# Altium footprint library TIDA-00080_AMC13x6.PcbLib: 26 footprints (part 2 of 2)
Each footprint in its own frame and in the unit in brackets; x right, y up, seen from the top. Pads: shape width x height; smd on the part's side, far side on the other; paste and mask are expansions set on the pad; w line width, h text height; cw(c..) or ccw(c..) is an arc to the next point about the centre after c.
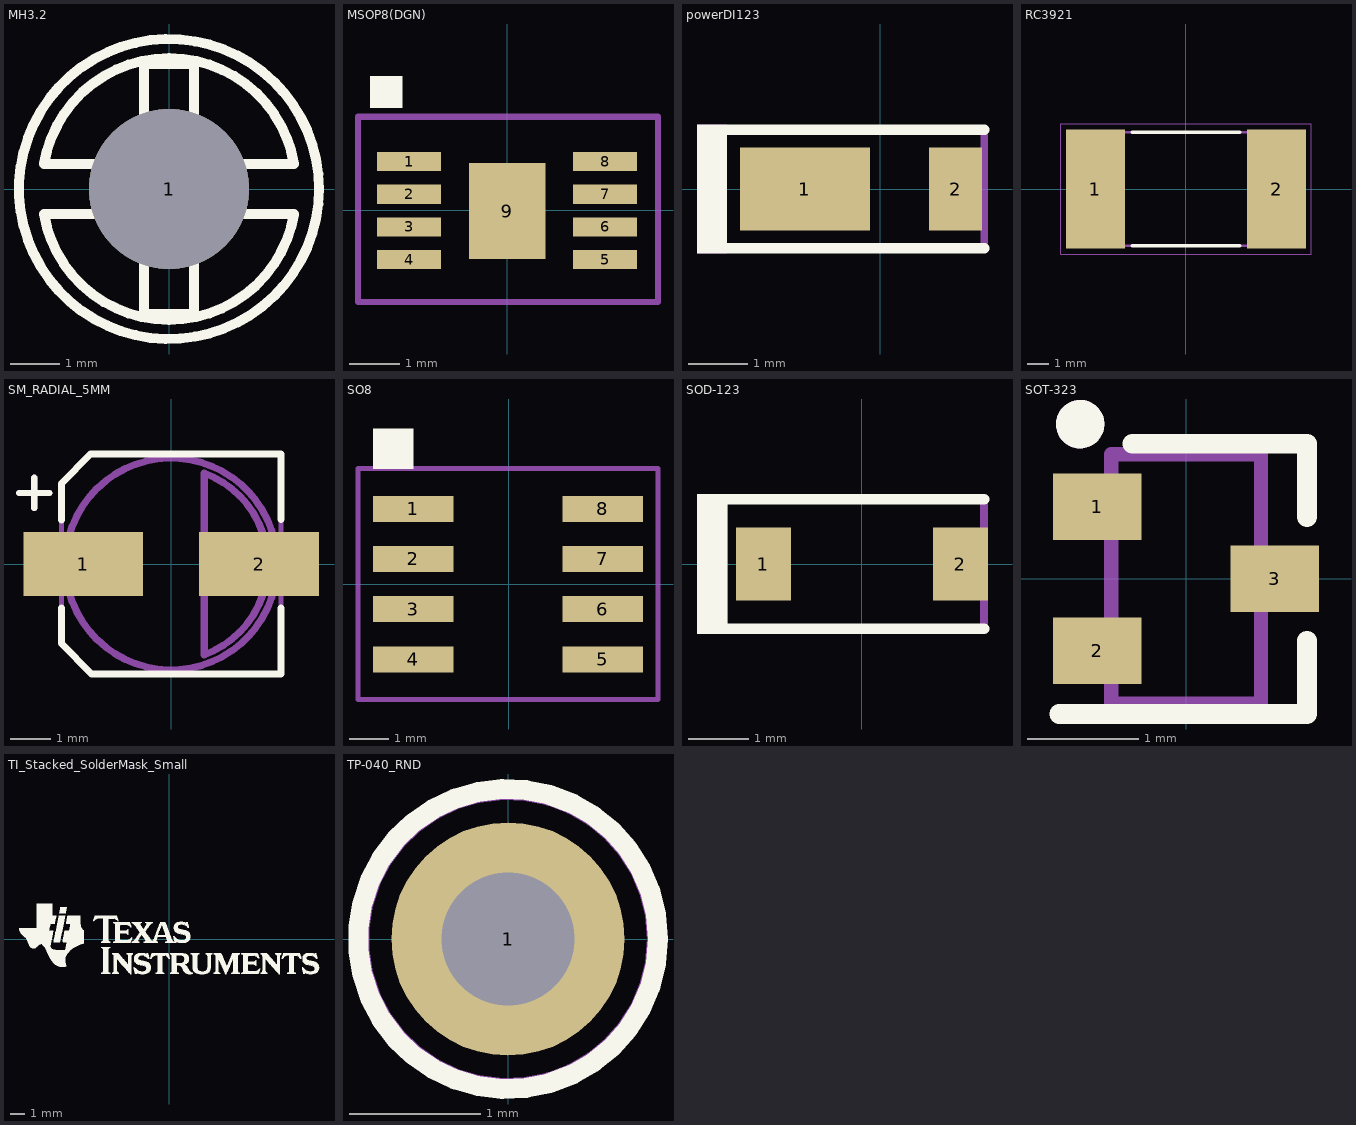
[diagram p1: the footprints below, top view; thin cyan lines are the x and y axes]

## MH3.2 [mil]
height 80
pads (1):
  round 128 / inner round 142 / far side round 128 hole 128 unplated mask+10: 1(0,0)
Top Overlay:
  circle w8: c0,0 r120
  lines w8: -100,-20 -20,-20 -20,-100 20,-100 20,-20 100,-20 ; -100.02,-19.91 ccw(c0,-3.35) 99.99,-20.08 ; -100,20 -20,20 -20,100 20,100 20,20 100,20 ; -99.99,20.09 cw(c0,3.36) 100.02,19.92

## MSOP8(DGN) [mil]
pads (9):
  rect 50x15 smd mask+3: 1(-77,38) 2(-77,12.4) 3(-77,-13.2) 4(-77,-38.8) 5(76.6,-38.8) 6(76.6,-13.2) 7(76.6,12.4) 8(76.6,38)
  rect 60x75 smd: 9(0,-0.8)
Top Overlay:
  region: -107.5,105 -82.5,105 -82.5,80 -107.5,80
Mechanical 5:
  lines w5: -117,-72 -117,73 118,73 118,-72 -117,-72
  text ".Designator" at 15,-20 h25
  text "*" at -105,30 h25

## powerDI123 [mm] "Diodes Inc recommended land pattern, document number DS30628 Rev. 6-2"
height 1
pads (2):
  rect 2.2x1.4 smd: 1(-1.275,0)
  rect 0.9x1.4 smd: 2(1.275,0)
Top Overlay:
  rectangle: -3.099,-1.092 -2.591,1.092
  lines w0.178: -2.946,-1.003 1.759,-1.003 ; -2.946,1.003 1.759,1.003
Mechanical 5:
  rectangle: -3.099,-1.092 -2.591,1.092
  lines w0.127: -2.946,-1.003 1.759,-1.003 1.759,1.003 -2.946,1.003
  text ".Designator" at -0.968,-0.366 h0.64
3D body "PowerDI123.stp": height 1, standoff 0, extent -2.375,-0.965 1.525,0.965

## RC3921 [mm] "RESISTOR, SMD, 3921"
height 0.93
pads (2):
  rect 2.7x5.45 smd mask+0.102: 1(-4.15,0) 2(4.15,0)
Top Overlay:
  lines w0.178: -2.45,-2.6 2.45,-2.6 ; -2.45,2.6 2.45,2.6
Mechanical 5:
  lines w0.127: -5,-2.6 -5,2.6 5,2.6 5,-2.6 -5,-2.6
  text ".Designator" at -0.66,-0.381 h0.64
Mechanical 15:
  lines w0.05: -5.75,-3 5.75,-3 5.75,3 -5.75,3 -5.75,-3
3D body: height 0.93, standoff 0, extent -5,-2.6 5,2.6

## SM_RADIAL_5MM [mm] "Nichicon 5x5.8"
height 6.1
pads (2):
  rect 3x1.6 smd: 1(-2.2,0) 2(2.2,0)
Top Overlay:
  lines w0.152: -3.81,1.778 -3.048,1.778 ; -3.429,1.397 -3.429,2.159
  lines w0.178: -2.75,-1.108 -2.75,-1.992 -1.992,-2.75 2.75,-2.75 2.75,-1.108 ; -2.75,1.108 -2.75,2.019 -2.019,2.75 2.75,2.75 2.75,1.118
Mechanical 5:
  lines w0.127: -2.75,-1.992 -2.75,2.019 -2.019,2.75 2.75,2.75 2.75,-2.75 -1.992,-2.75 -2.75,-1.992
  lines w0.152: -3.81,1.778 -3.048,1.778 ; -3.429,1.397 -3.429,2.159
  text ".Designator" at -0.372,1.111 h0.64
Mechanical 13:
  circle w0.178: c0,0 r2.65
  lines w0.178: 0.827,-2.273 ccw(c0,0) 0.827,2.273 0.827,-2.273
3D body: height 1, standoff 0, extent -2.751,-2.751 2.751,2.751
3D body: height 6.1, standoff 1, extent -2.649,-2.649 2.649,2.649
3D body: height 6.1, standoff 6, extent 0.827,-2.274 2.42,2.274

## SO8 [mil]
pads (8):
  rect 80x26 smd: 1(-95,75) 2(-95,25) 3(-95,-25) 4(-95,-75) 5(94,-75) 6(94,-25) 7(94,25) 8(94,75)
Top Overlay:
  region: -95,115 -95,155 -135,155 -135,115
Mechanical 5:
  lines w5: -150,-115 -150,115 149,115 149,-115 -150,-115
  text "*" at -55.9,51.4 h25
  text ".Designator" at -28.61,-6.81 h25

## SOD-123 [mm] "On Semi recommended land pattern"
height 1.35
pads (2):
  rect 0.915x1.22 smd: 1(-1.637,0) 2(1.637,0)
Top Overlay:
  rectangle: -2.743,-1.168 -2.235,1.168
  lines w0.178: -2.413,-1.079 2.032,-1.079 ; -2.413,1.079 2.032,1.079
Mechanical 5:
  rectangle: -2.743,-1.168 -2.235,1.168
  lines w0.127: -2.413,-1.079 2.032,-1.079 2.032,1.079 -2.413,1.079
  text ".Designator" at 0.762,0.381 h0.64
3D body "SOD-123.stp": height 1.35, standoff 0, extent -1.932,-0.9 1.932,0.9

## SOT-323 [mm] "Zetex recommended land pattern.  March 2007"
height 1.1
pads (3):
  rect 0.8x0.6 smd: 1(-0.8,0.65) 2(-0.8,-0.65) 3(0.8,0)
Top Overlay:
  circle w0.254: c-0.955,1.397 r0.092
  lines w0.178: -1.143,-1.219 1.092,-1.219 1.092,-0.559 ; -0.483,1.219 1.092,1.219 1.092,0.559
Mechanical 5:
  circle w0.254: c-0.955,1.397 r0.092
  lines w0.127: -1.125,-0.8 -1.125,-0.5 -0.975,-0.5 -0.935,-0.5 -0.884,-0.5 -0.725,-0.5 -0.675,-0.5 -0.675,-0.8 -0.725,-0.8 -0.884,-0.8 -0.935,-0.8 -0.975,-0.8 -1.125,-0.8 ; -1.125,0.5 -1.125,0.8 -0.975,0.8 -0.935,0.8 -0.884,0.8 -0.725,0.8 -0.675,0.8 -0.675,0.5 -0.725,0.5 -0.884,0.5 -0.935,0.5 -0.975,0.5 -1.125,0.5 ; -0.675,-1.125 -0.675,1.125 0.675,1.125 0.675,-1.125 -0.675,-1.125 ; 0.675,-0.15 0.725,-0.15 0.884,-0.15 0.935,-0.15 0.975,-0.15 1.125,-0.15 1.125,0.15 0.975,0.15 0.935,0.15 0.884,0.15 0.725,0.15 0.675,0.15 0.675,-0.15
  text ".Designator" at 0.364,-0.912 h0.64
3D body "SC-70.stp": height 1.13, standoff 0.02, extent -1.125,-1.125 1.125,1.125

## TI_Stacked_SolderMask_Small [mil]
pads (1):
  rect 0x0 on Top Overlay paste-125 mask-125: 0(0,0)
Top Overlay:
  drawing of 18 lines, arcs and shapes, not listed

## TP-040_RND [mil]
pads (1):
  round 70 / inner round 62 / far side round 62 hole 40: 1(0,0)
Top Overlay:
  circle w6: c0,0 r45
Mechanical 5:
  circle w6: c0,0 r44.72
  text ".Designator" at -33,-81 h25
